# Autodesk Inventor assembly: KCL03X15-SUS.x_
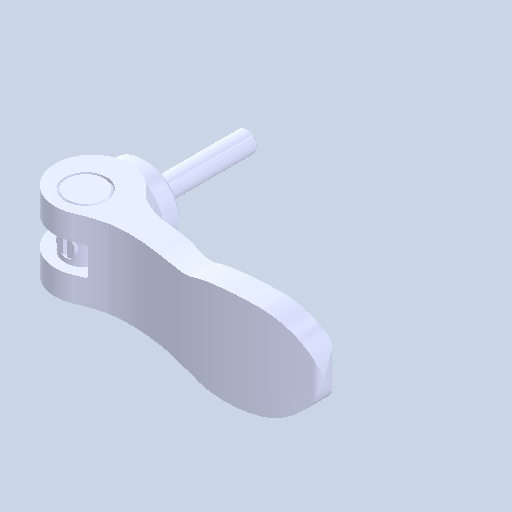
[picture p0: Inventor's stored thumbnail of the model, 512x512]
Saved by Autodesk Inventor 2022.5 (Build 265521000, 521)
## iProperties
Created: 2024-08
Part Number: KCL03X15-SUS.x_
Document SubType Name: Assembly
Designer: ImaoCorp
Author: ImaoCorp
Sending System: SOLIDWORKS 2022-2022290
MC: AMD64
MC_MODEL: Intel64 Family 6 Model 60 Stepping 3, GenuineIntel
OS: Windows_NT
FRU: Parasolid Version 33.1, build 260,  4-25-2022
FORMAT: text
GUISE: transmit
KEY: FILEKCL03X15-SUS.x_t
DATE: Thu Aug 29 10:46:52 2024
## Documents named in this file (5)
- Y:\5.更新分\2024年対応\1001_KCL\データ\kcl03x15-sus\KCL03X15-SUS.x_.iam
- Y:\5.更新分\2024年対応\1001_KCL\データ\kcl03x15-sus\KCL03X15-SUS_01.ipt
- Y:\5.更新分\2024年対応\1001_KCL\データ\kcl03x15-sus\KCL03X15-SUS_02.ipt
- Y:\5.更新分\2024年対応\1001_KCL\データ\kcl03x15-sus\KCL03X15-SUS_03.ipt
- Y:\5.更新分\2024年対応\1001_KCL\データ\kcl03x15-sus\KCL03X15-SUS_04.ipt
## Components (4 placed, 4 different names)
1. KCL03X15-SUS_01
2. KCL03X15-SUS_02
3. KCL03X15-SUS_03
4. KCL03X15-SUS_04
